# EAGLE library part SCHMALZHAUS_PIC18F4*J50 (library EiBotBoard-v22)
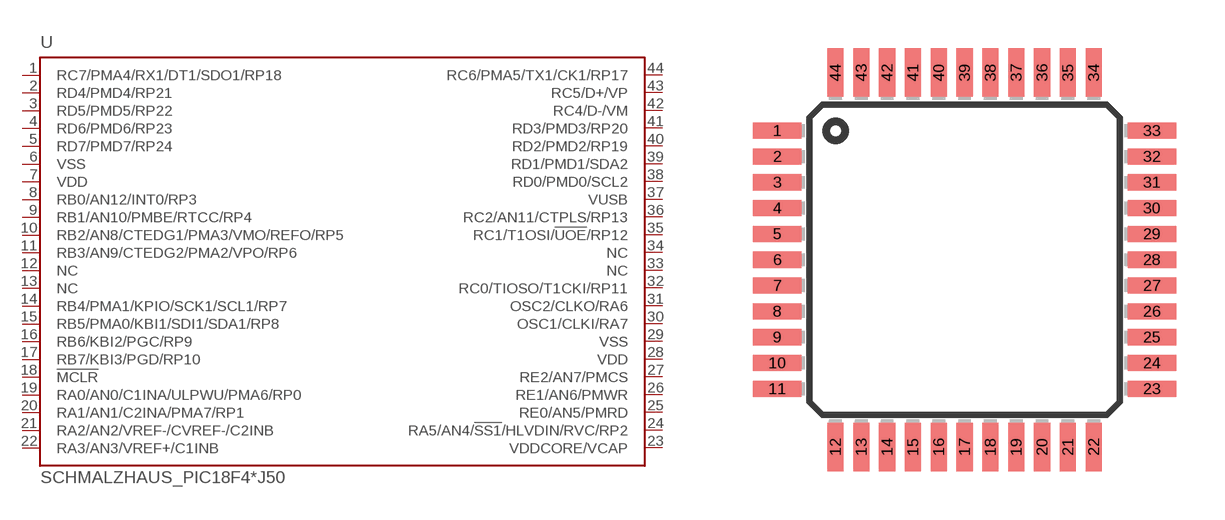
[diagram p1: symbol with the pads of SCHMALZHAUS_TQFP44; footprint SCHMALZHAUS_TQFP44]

Designator prefix -

## SCHMALZHAUS_PIC18F4J50  [SCHMALZHAUS_TQFP44]
1  RC7/PMA4/RX1/DT1/SDO1/RP18
2  RD4/PMD4/RP21
3  RD5/PMD5/RP22
4  RD6/PMD6/RP23
5  RD7/PMD7/RP24
6  VSS  pwr
7  VDD  pwr
8  RB0/AN12/INT0/RP3
9  RB1/AN10/PMBE/RTCC/RP4
10  RB2/AN8/CTEDG1/PMA3/VMO/REFO/RP5
11  RB3/AN9/CTEDG2/PMA2/VPO/RP6
12  NC
13  NC
14  RB4/PMA1/KPIO/SCK1/SCL1/RP7
15  RB5/PMA0/KBI1/SDI1/SDA1/RP8
16  RB6/KBI2/PGC/RP9
17  RB7/KBI3/PGD/RP10
18  !MCLR!  in
19  RA0/AN0/C1INA/ULPWU/PMA6/RP0
20  RA1/AN1/C2INA/PMA7/RP1
21  RA2/AN2/VREF-/CVREF-/C2INB
22  RA3/AN3/VREF+/C1INB
23  VDDCORE/VCAP
24  RA5/AN4/!SS1!/HLVDIN/RVC/RP2
25  RE0/AN5/PMRD
26  RE1/AN6/PMWR
27  RE2/AN7/PMCS
28  VDD  pwr
29  VSS  pwr
30  OSC1/CLKI/RA7  in
31  OSC2/CLKO/RA6  out
32  RC0/TIOSO/T1CKI/RP11
33  NC  in
34  NC  in
35  RC1/T1OSI/!UOE!/RP12
36  RC2/AN11/CTPLS/RP13
37  VUSB
38  RD0/PMD0/SCL2
39  RD1/PMD1/SDA2
40  RD2/PMD2/RP19
41  RD3/PMD3/RP20
42  RC4/D-/VM
43  RC5/D+/VP
44  RC6/PMA5/TX1/CK1/RP17

## Footprint SCHMALZHAUS_TQFP44 (pad centres in mm)
Thin Quad Flat Pack package type TQ
smd 1.5 x 0.5: 1 -5.8,4; 2 -5.8,3.2; 3 -5.8,2.4; 4 -5.8,1.6; 5 -5.8,0.8; 6 -5.8,0; 7 -5.8,-0.8; 8 -5.8,-1.6; 9 -5.8,-2.4; 10 -5.8,-3.2; 11 -5.8,-4; 23 5.8,-4; 24 5.8,-3.2; 25 5.8,-2.4; 26 5.8,-1.6; 27 5.8,-0.8; 28 5.8,0; 29 5.8,0.8; 30 5.8,1.6; 31 5.8,2.4; 32 5.8,3.2; 33 5.8,4
smd 0.5 x 1.5: 12 -4,-5.8; 13 -3.2,-5.8; 14 -2.4,-5.8; 15 -1.6,-5.8; 16 -0.8,-5.8; 17 0,-5.8; 18 0.8,-5.8; 19 1.6,-5.8; 20 2.4,-5.8; 21 3.2,-5.8; 22 4,-5.8; 34 4,5.8; 35 3.2,5.8; 36 2.4,5.8; 37 1.6,5.8; 38 0.8,5.8; 39 0,5.8; 40 -0.8,5.8; 41 -1.6,5.8; 42 -2.4,5.8; 43 -3.2,5.8; 44 -4,5.8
